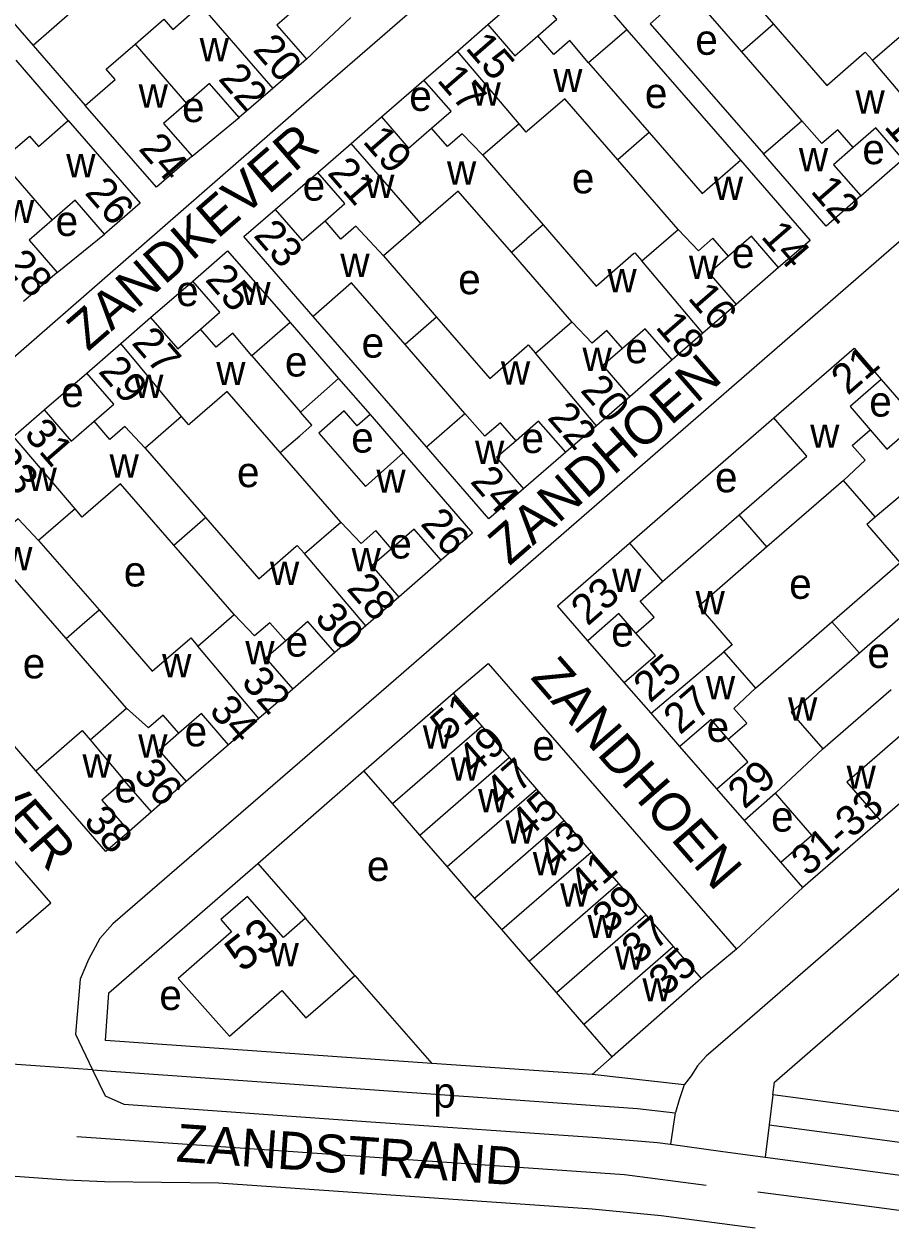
# Model space of a CAD drawing. Extents: x 155854 to 157362, y 383621 to 384685.
# Drawn here: x 156071.1 to 156185.4, y 383977 to 384135.3 of the extents above; entities that cross this region are included whole.
import ezdxf

# ---------------------------------------------------------------- set-up
doc = ezdxf.new("R2010")
doc.units = 0
for name, color, linetype in [('BLT_Basislijn', 7, 'Continuous'), ('BLT_Bebouwing', 7, 'Continuous'), ('BLT_Centroide', 7, 'Continuous'), ('BLT_Huisnummer', 7, 'Continuous'), ('BLT_Huisnummer_ tussenligend', 7, 'Continuous'), ('BLT_Huisnummer_reeks', 7, 'Continuous'), ('BLT_Onderverdeling_panden', 7, 'Continuous'), ('BLT_Straatnaam', 7, 'Continuous'), ('BLT_Vlakafsluiter', 7, 'Continuous')]:
    doc.layers.add(name, color=color, linetype=linetype)

msp = doc.modelspace()

# ---------------------------------------------------------------- linework, layer by layer
at = {"layer": 'BLT_Basislijn'}
for p, q in [((156182.59, 384189.41), (156111.16, 384127.33)), ((156228.99, 384143.37), (156119.21, 384047.9)), ((156132.32, 384135.17), (156137.86, 384139.98)), ((156080.23, 384139.36), (156072.3, 384132.42)), ((156108.36, 384130.6), (156114.21, 384136.12)), ((156153.72, 384135.29), (156168.72, 384118.08)), ((156150.68, 384134.48), (156165.66, 384117.25)), ((156072.3, 384132.42), (156079.17, 384124.5)), ((156076.93, 384122.52), (156070.03, 384130.46)), ((156111.16, 384127.33), (155991.68, 384023.17)), ((156118.28, 384122.97), (156123.88, 384127.84)), ((156093.27, 384117.78), (156099.48, 384122.89)), ((156181.54, 384112.55), (156187.1, 384117.41)), ((156104.24, 384110.77), (156109.85, 384115.65)), ((156075.46, 384102.45), (156081.72, 384107.5)), ((156170.68, 384103.1), (156165.08, 384098.22)), ((156087.8, 384096.48), (156093.36, 384101.29)), ((156106.2, 384095.82), (156112.6, 384088.45)), ((156124.22, 384079.4), (156109.27, 384096.63)), ((156156.64, 384090.89), (156151.04, 384086.03)), ((156073.76, 384084.28), (156079.36, 384089.14)), ((156184.24, 384088.28), (156189.1, 384082.69)), ((156116.76, 384083.66), (156121.15, 384078.61)), ((156151, 384066.68), (156170.05, 384083.24)), ((156142.6, 384078.7), (156137.04, 384073.86)), ((156126.15, 384064.42), (156120.57, 384059.57)), ((156150.32, 384048.28), (156145.51, 384053.8)), ((156112.13, 384052.23), (156106.56, 384047.39)), ((156127.74, 384046.86), (156132.34, 384050.8)), ((156203.42, 384046.86), (156184.1, 384030.05)), ((156072.64, 384036.63), (156066.69, 384043.48)), ((156098.08, 384040.05), (156092.49, 384035.2)), ((156162.53, 384034.22), (156157.67, 384039.83)), ((156101.95, 384024.4), (156115.95, 384036.63)), ((156087.9, 384031.2), (156084.96, 384028.62)), ((156170.97, 384024.54), (156166.17, 384030.06)), ((156101.95, 384024.4), (156108.25, 384017.14)), ((156173.9, 384021.19), (156165.13, 384013.05)), ((156114.76, 384009.61), (156124.9, 383997.99)), ((156158.22, 383995.14), (156146.09, 383996.5)), ((156169.94, 383993.83), (156169.45, 383989.86)), ((156169.45, 383989.86), (156168.92, 383985.6))]:
    msp.add_line(p, q, dxfattribs=at)
for points in [[(156150.65, 384224.45), (156146.11, 384229.67), (156055.9, 384151.3), (156072.3, 384132.42)], [(156271.3, 384094.61), (156165.88, 384003.01), (156161.13, 383998.95)], [(156169.94, 383993.83), (156170.15, 383995.49), (156269.03, 384081.38)], [(156070.04, 384015.24), (156074.62, 384019.2), (156041.83, 384056.94), (156037.26, 384052.98)], [(156132.34, 384050.8), (156165.13, 384013.05)], [(156119.21, 384047.9), (156082.8, 384016.41), (156081.09, 384014.48), (156079.59, 384011.7), (156078.52, 384009.12), (156077.88, 384001.84), (156080.14, 383997.12)], [(156081.83, 384001.02), (156082.27, 384007.3), (156101.95, 384024.4)], [(156165.13, 384013.05), (156160.47, 384009.18)], [(156124.9, 383997.99), (156081.83, 384001.02)], [(156161.13, 383998.95), (156159.98, 383997.65), (156159.15, 383996.34), (156158.22, 383995.14)], [(156146.09, 383996.5), (156124.9, 383997.99)], [(156148.71, 383998.87), (156146.09, 383996.5)], [(156080.14, 383997.12), (156081.78, 383993.72), (156084.26, 383992.58)], [(156080.14, 383997.12), (156152.08, 383992.01), (156157.06, 383991.45)], [(156158.22, 383995.14), (156157.57, 383993.18), (156157.09, 383991.48)], [(156158.06, 383994.64), (156158.05, 383994.63)], [(156084.26, 383992.58), (156116.24, 383990.33), (156146.75, 383988.19)], [(156208.6, 383988.69), (156169.94, 383993.83)], [(156157.06, 383991.45), (156156.41, 383987.31)], [(156169.45, 383989.86), (156266.3, 383977), (156363.4, 383964.11)], [(156078.08, 383988.34), (156150.36, 383983.33), (156161.14, 383981.92)], [(156146.75, 383988.19), (156154.72, 383987.54), (156156.41, 383987.31)], [(156156.41, 383987.31), (156163.02, 383986.39), (156168.92, 383985.6)], [(156168.92, 383985.6), (156189.73, 383982.81)], [(156167.61, 383976.23), (156155.21, 383977.85), (156146.07, 383978.71), (156096.76, 383982.18), (156081.71, 383982.35), (156076.66, 383982.58), (156069.91, 383983.06), (156060.92, 383984.14)], [(156167.95, 383981.03), (156181.65, 383979.24), (156217.42, 383974.51), (156229.18, 383972.97)]]:
    msp.add_lwpolyline(points, dxfattribs=at)
at = {"layer": 'BLT_Bebouwing'}
for p, q in [((156128.3, 384131.68), (156132.32, 384135.17)), ((156108.36, 384130.6), (156103.92, 384126.74)), ((156123.88, 384127.84), (156128.3, 384131.68)), ((156103.92, 384126.74), (156099.48, 384122.89)), ((156114.26, 384119.48), (156118.28, 384122.97)), ((156109.85, 384115.65), (156114.26, 384119.48)), ((156100.09, 384107.17), (156104.24, 384110.77)), ((156123.47, 384108.9), (156118.53, 384104.62)), ((156109.27, 384096.63), (156100.09, 384107.17)), ((156118.53, 384104.62), (156125.55, 384096.53)), ((156075.46, 384102.45), (156071.02, 384098.59)), ((156165.08, 384098.22), (156160.69, 384094.4)), ((156083.85, 384093.05), (156087.8, 384096.48)), ((156160.69, 384094.4), (156156.64, 384090.89)), ((156079.36, 384089.14), (156083.85, 384093.05)), ((156101.14, 384091.43), (156107.59, 384084)), ((156107.59, 384084), (156112.6, 384088.45)), ((156112.6, 384088.45), (156116.76, 384083.66)), ((156151.04, 384086.03), (156146.64, 384082.2)), ((156069.72, 384080.79), (156073.76, 384084.28)), ((156146.64, 384082.2), (156142.6, 384078.7)), ((156120.57, 384059.57), (156116.22, 384055.78)), ((156116.22, 384055.78), (156112.13, 384052.23)), ((156106.56, 384047.39), (156102.1, 384043.53)), ((156115.95, 384036.63), (156127.74, 384046.86)), ((156127.74, 384046.86), (156131.51, 384042.52)), ((156102.1, 384043.53), (156098.08, 384040.05)), ((156131.52, 384042.52), (156135.12, 384038.37)), ((156135.12, 384038.36), (156138.74, 384034.2)), ((156087.9, 384031.2), (156084.33, 384035.31)), ((156119.72, 384032.29), (156115.95, 384036.63)), ((156092.49, 384035.2), (156087.9, 384031.2)), ((156138.74, 384034.2), (156142.35, 384030.04)), ((156123.32, 384028.14), (156119.72, 384032.29)), ((156142.35, 384030.04), (156145.95, 384025.89)), ((156126.94, 384023.97), (156123.32, 384028.14)), ((156145.95, 384025.89), (156149.56, 384021.74)), ((156130.55, 384019.81), (156126.94, 384023.97)), ((156149.56, 384021.74), (156153.17, 384017.59)), ((156100.59, 384020.03), (156097.06, 384016.97)), ((156105.34, 384014.59), (156100.59, 384020.03)), ((156134.15, 384015.66), (156130.55, 384019.81)), ((156097.06, 384016.97), (156098.48, 384015.36)), ((156108.25, 384017.14), (156105.34, 384014.59)), ((156114.76, 384009.61), (156108.25, 384017.14)), ((156153.17, 384017.59), (156156.78, 384013.43)), ((156098.48, 384015.36), (156091.44, 384009.19)), ((156137.76, 384011.49), (156134.15, 384015.66)), ((156156.78, 384013.43), (156160.47, 384009.18)), ((156141.37, 384007.34), (156137.76, 384011.49)), ((156091.44, 384009.19), (156098.19, 384001.58)), ((156108.3, 384004.01), (156114.76, 384009.61)), ((156160.47, 384009.18), (156148.71, 383998.87)), ((156098.19, 384001.58), (156105.14, 384007.63)), ((156105.14, 384007.63), (156108.3, 384004.01)), ((156144.98, 384003.18), (156141.37, 384007.34)), ((156148.71, 383998.87), (156144.98, 384003.18))]:
    msp.add_line(p, q, dxfattribs=at)
for points in [[(156137.86, 384139.98), (156142.46, 384143.98), (156150.68, 384134.48)], [(156162.05, 384144.39), (156170.02, 384135.21)], [(156138.9, 384133.67), (156141.44, 384135.87), (156137.86, 384139.98)], [(156165.85, 384131.58), (156158.75, 384139.74), (156153.72, 384135.29)], [(156085.74, 384132.59), (156089.53, 384135.88), (156090.71, 384134.52), (156094.39, 384137.72)], [(156107.5, 384137.72), (156104.46, 384135.08), (156108.14, 384130.85), (156108.36, 384130.6)], [(156132.32, 384135.17), (156135.89, 384131.06), (156138.9, 384133.67)], [(156170.02, 384135.21), (156177.05, 384127.13), (156181.99, 384131.43)], [(156150.68, 384134.48), (156145.6, 384130.12)], [(156183.08, 384130.45), (156187.88, 384134.62)], [(156079.17, 384124.5), (156083.12, 384127.93), (156081.93, 384129.29), (156085.74, 384132.59)], [(156173.77, 384122.47), (156165.85, 384131.58)], [(156181.99, 384131.43), (156182.13, 384131.54), (156183.08, 384130.45)], [(156145.6, 384130.12), (156153.61, 384120.91)], [(156099.48, 384122.89), (156095.59, 384127.37), (156092.55, 384124.74)], [(156124.87, 384121.48), (156127.46, 384123.73), (156123.88, 384127.84)], [(156093.27, 384117.78), (156088.57, 384113.69), (156079.17, 384124.5)], [(156092.55, 384124.74), (156089.52, 384122.1), (156093.27, 384117.78)], [(156149.47, 384117.3), (156142.46, 384125.38), (156137.51, 384121.1)], [(156068.01, 384117.16), (156071.8, 384120.45), (156072.99, 384119.09), (156076.93, 384122.52)], [(156076.93, 384122.52), (156086.42, 384111.58), (156081.72, 384107.5)], [(156118.28, 384122.97), (156121.86, 384118.86), (156124.87, 384121.48)], [(156168.72, 384118.08), (156173.77, 384122.47)], [(156136.43, 384122.07), (156131.63, 384117.91)], [(156137.51, 384121.1), (156137.38, 384120.98), (156136.43, 384122.07)], [(156153.61, 384120.91), (156160.6, 384112.86), (156165.66, 384117.25)], [(156187.1, 384117.41), (156183.52, 384121.52), (156180.55, 384118.92)], [(156131.63, 384117.91), (156139.6, 384108.72)], [(156181.54, 384112.55), (156176.97, 384108.55), (156168.72, 384118.08)], [(156180.55, 384118.92), (156177.95, 384116.65), (156181.54, 384112.55)], [(156157.44, 384108.12), (156149.47, 384117.3)], [(156165.66, 384117.25), (156174.84, 384106.67), (156170.68, 384103.1)], [(156110.82, 384109.27), (156113.42, 384111.53), (156109.85, 384115.65)], [(156135.43, 384105.1), (156128.41, 384113.19), (156123.47, 384108.9)], [(156081.72, 384107.5), (156077.85, 384111.96), (156074.81, 384109.32)], [(156104.24, 384110.77), (156107.81, 384106.66), (156110.82, 384109.27)], [(156074.81, 384109.32), (156071.78, 384106.68), (156075.46, 384102.45)], [(156139.6, 384108.72), (156146.62, 384100.64), (156151.56, 384104.93)], [(156152.64, 384103.96), (156157.44, 384108.12)], [(156170.68, 384103.1), (156167.13, 384107.24), (156164.1, 384104.6)], [(156093.36, 384101.29), (156097.93, 384105.29), (156106.2, 384095.82)], [(156143.39, 384095.93), (156135.43, 384105.1)], [(156151.56, 384104.93), (156151.7, 384105.04), (156152.64, 384103.96)], [(156164.1, 384104.6), (156161.51, 384102.33), (156165.08, 384098.22)], [(156094.37, 384094.96), (156096.94, 384097.18), (156093.36, 384101.29)], [(156121.38, 384092.91), (156114.3, 384101.06), (156109.27, 384096.63)], [(156087.8, 384096.48), (156091.37, 384092.36), (156094.37, 384094.96)], [(156106.2, 384095.82), (156101.14, 384091.43)], [(156125.55, 384096.53), (156132.57, 384088.45), (156137.51, 384092.74)], [(156138.59, 384091.77), (156143.39, 384095.93)], [(156156.64, 384090.89), (156153.07, 384095.01), (156150.08, 384092.41)], [(156129.29, 384083.81), (156121.38, 384092.91)], [(156137.51, 384092.74), (156137.65, 384092.86), (156138.59, 384091.77)], [(156150.08, 384092.41), (156147.47, 384090.14), (156151.04, 384086.03)], [(156170.05, 384083.24), (156180.65, 384092.45), (156184.24, 384088.28)], [(156080.35, 384082.78), (156082.93, 384085.03), (156079.36, 384089.14)], [(156184.24, 384088.28), (156180.12, 384084.72), (156182.78, 384081.65)], [(156104.92, 384078.64), (156097.9, 384086.72), (156092.96, 384082.43)], [(156073.76, 384084.28), (156077.33, 384080.15), (156080.35, 384082.78)], [(156091.88, 384083.41), (156087.08, 384079.24)], [(156092.96, 384082.43), (156092.83, 384082.31), (156091.88, 384083.41)], [(156116.76, 384083.66), (156115.08, 384082.2), (156113.35, 384084.17), (156110.02, 384081.21), (156116.15, 384074.16), (156121.15, 384078.61)], [(156124.22, 384079.4), (156129.29, 384083.81)], [(156142.6, 384078.7), (156139.02, 384082.81), (156136.04, 384080.22)], [(156165.49, 384070.41), (156174.44, 384078.18), (156170.05, 384083.24)], [(156182.78, 384081.65), (156184.99, 384079.11), (156189.1, 384082.69)], [(156136.04, 384080.22), (156133.46, 384077.98), (156137.04, 384073.86)], [(156087.08, 384079.24), (156095.05, 384070.06)], [(156112.89, 384069.46), (156104.92, 384078.64)], [(156121.15, 384078.61), (156130.3, 384068), (156126.15, 384064.42)], [(156137.04, 384073.86), (156132.45, 384069.89), (156124.22, 384079.4)], [(156179.28, 384074.97), (156169.16, 384066.18)], [(156183.45, 384070.17), (156179.28, 384074.97)], [(156090.87, 384066.43), (156083.84, 384074.52), (156078.9, 384070.23)], [(156077.82, 384071.2), (156073.02, 384067.03)], [(156078.9, 384070.23), (156078.77, 384070.11), (156077.82, 384071.2)], [(156155.38, 384061.63), (156165.49, 384070.41)], [(156182.46, 384069.07), (156182.34, 384069.21), (156183.45, 384070.17)], [(156095.05, 384070.06), (156102.08, 384061.98), (156107.01, 384066.27)], [(156108.09, 384065.3), (156112.89, 384069.46)], [(156126.15, 384064.42), (156122.59, 384068.54), (156119.61, 384065.95)], [(156177.74, 384056.31), (156186.75, 384064.13), (156182.46, 384069.07)], [(156073.02, 384067.03), (156080.99, 384057.86)], [(156098.83, 384057.26), (156090.87, 384066.43)], [(156107.01, 384066.27), (156107.15, 384066.38), (156108.09, 384065.3)], [(156119.61, 384065.95), (156116.99, 384063.68), (156120.57, 384059.57)], [(156145.51, 384053.8), (156141.49, 384058.4), (156151, 384066.68)], [(156151, 384066.68), (156155.38, 384061.63)], [(156169.16, 384066.18), (156160.16, 384058.36), (156164.57, 384053.28)], [(156076.63, 384054.1), (156069.61, 384062.18), (156064.78, 384057.98)], [(156191.44, 384060.91), (156181.36, 384052.14)], [(156080.99, 384057.86), (156088.02, 384049.77), (156092.96, 384054.06)], [(156094.03, 384053.09), (156098.83, 384057.26)], [(156112.13, 384052.23), (156108.56, 384056.34), (156105.63, 384053.8)], [(156151.86, 384054.82), (156149.61, 384057.39), (156145.51, 384053.8)], [(156167.63, 384047.52), (156177.74, 384056.31)], [(156150.32, 384048.28), (156154.43, 384051.86), (156151.86, 384054.82)], [(156084.63, 384044.9), (156076.63, 384054.1)], [(156092.96, 384054.06), (156093.09, 384054.18), (156094.03, 384053.09)], [(156105.63, 384053.8), (156103, 384051.51), (156106.56, 384047.39)], [(156164.57, 384053.28), (156163.46, 384052.32)], [(156163.46, 384052.32), (156167.63, 384047.52)], [(156181.36, 384052.14), (156172.35, 384044.32), (156176.52, 384039.53)], [(156153.85, 384044.22), (156150.32, 384048.28)], [(156176.52, 384039.53), (156185.53, 384047.36)], [(156079.83, 384040.73), (156084.63, 384044.9)], [(156098.08, 384040.05), (156094.52, 384044.18), (156091.53, 384041.58)], [(156157.67, 384039.83), (156153.85, 384044.22)], [(156161.78, 384043.41), (156157.67, 384039.83)], [(156164.04, 384040.79), (156161.78, 384043.41)], [(156189.07, 384043.28), (156179.68, 384035.12), (156184.1, 384030.05)], [(156072.64, 384036.63), (156078.78, 384041.94), (156079.83, 384040.73)], [(156091.53, 384041.58), (156088.91, 384039.3), (156092.49, 384035.2)], [(156166.63, 384037.81), (156164.04, 384040.79)], [(156162.53, 384034.22), (156166.63, 384037.81)], [(156084.96, 384028.62), (156081.9, 384025.96), (156072.64, 384036.63)], [(156084.33, 384035.31), (156081.37, 384032.73), (156084.96, 384028.62)], [(156166.17, 384030.06), (156162.53, 384034.22)], [(156170.28, 384033.65), (156166.17, 384030.06)], [(156175.07, 384028.13), (156170.28, 384033.65)], [(156184.1, 384030.05), (156173.9, 384021.19)], [(156170.97, 384024.54), (156175.07, 384028.13)], [(156173.9, 384021.19), (156170.97, 384024.54)]]:
    msp.add_lwpolyline(points, dxfattribs=at)
at = {"layer": 'BLT_Onderverdeling_panden'}
for p, q in [((156094.39, 384137.72), (156103.92, 384126.74)), ((156085.74, 384132.59), (156092.55, 384124.74)), ((156136.43, 384122.07), (156128.31, 384131.68)), ((156191.13, 384120.92), (156183.08, 384130.45)), ((156123.47, 384108.9), (156114.26, 384119.48)), ((156068.01, 384117.16), (156074.81, 384109.32)), ((156160.69, 384094.4), (156152.64, 384103.96)), ((156125.55, 384096.53), (156121.38, 384092.91)), ((156091.88, 384083.41), (156083.85, 384093.05)), ((156146.64, 384082.2), (156138.59, 384091.77)), ((156077.82, 384071.2), (156069.72, 384080.79)), ((156183.45, 384070.17), (156193, 384078.22)), ((156169.16, 384066.18), (156165.49, 384070.41)), ((156116.22, 384055.78), (156108.09, 384065.3)), ((156181.36, 384052.14), (156177.74, 384056.31)), ((156102.1, 384043.53), (156094.03, 384053.09)), ((156153.85, 384044.22), (156163.46, 384052.32)), ((156119.72, 384032.29), (156131.52, 384042.52)), ((156079.83, 384040.73), (156084.33, 384035.31)), ((156170.28, 384033.65), (156176.52, 384039.53)), ((156123.32, 384028.14), (156135.12, 384038.36)), ((156126.94, 384023.97), (156138.74, 384034.2)), ((156130.55, 384019.81), (156142.35, 384030.04)), ((156134.15, 384015.66), (156145.95, 384025.89)), ((156137.76, 384011.49), (156149.56, 384021.74)), ((156141.37, 384007.34), (156153.17, 384017.59)), ((156144.98, 384003.18), (156156.78, 384013.43))]:
    msp.add_line(p, q, dxfattribs=at)
for points in [[(156170.02, 384135.21), (156165.85, 384131.58)], [(156145.6, 384130.12), (156143.12, 384133.06), (156141.02, 384131.23), (156138.9, 384133.67)], [(156180.55, 384118.92), (156178.5, 384121.28), (156176.39, 384119.45), (156173.77, 384122.47)], [(156131.63, 384117.91), (156128.93, 384120.76), (156126.97, 384119.06), (156124.87, 384121.48)], [(156153.61, 384120.91), (156151.94, 384119.45)], [(156151.94, 384119.45), (156149.47, 384117.3)], [(156118.53, 384104.62), (156114.89, 384108.56), (156112.92, 384106.85), (156110.82, 384109.27)], [(156139.6, 384108.72), (156137.46, 384106.87)], [(156164.1, 384104.6), (156162.03, 384106.97), (156160.12, 384105.29), (156157.44, 384108.12)], [(156135.43, 384105.1), (156137.46, 384106.87)], [(156150.08, 384092.41), (156148.02, 384094.79), (156146.07, 384093.1), (156143.39, 384095.93)], [(156101.14, 384091.43), (156098.63, 384094.43), (156096.46, 384092.55), (156094.37, 384094.96)], [(156087.08, 384079.24), (156084.38, 384082.09), (156082.42, 384080.39), (156080.35, 384082.78)], [(156107.48, 384080.88), (156109.09, 384082.28), (156107.59, 384084)], [(156136.04, 384080.22), (156133.98, 384082.59), (156131.91, 384080.8), (156129.29, 384083.81)], [(156179.28, 384074.97), (156182.11, 384077.66), (156180.42, 384079.6), (156182.78, 384081.65)], [(156104.92, 384078.64), (156107.48, 384080.88)], [(156073.02, 384067.03), (156070.3, 384069.89), (156068.38, 384068.21), (156066.3, 384070.61)], [(156090.87, 384066.43), (156095.05, 384070.07)], [(156119.61, 384065.95), (156117.53, 384068.34), (156115.57, 384066.63), (156112.89, 384069.46)], [(156151.86, 384054.82), (156154.27, 384056.92), (156152.44, 384059.03), (156155.38, 384061.63)], [(156078.76, 384055.93), (156080.99, 384057.86)], [(156076.63, 384054.1), (156078.76, 384055.93)], [(156105.63, 384053.8), (156103.52, 384056.17), (156101.51, 384054.43), (156098.83, 384057.26)], [(156164.04, 384040.79), (156166.48, 384042.91), (156164.8, 384044.84), (156167.63, 384047.52)], [(156091.53, 384041.58), (156089.45, 384043.98), (156087.5, 384042.29), (156084.63, 384044.9)]]:
    msp.add_lwpolyline(points, dxfattribs=at)
at = {"layer": 'BLT_Vlakafsluiter'}
msp.add_line((156080.14, 383997.12), (156066.34, 383998.09), dxfattribs=at)

# ---------------------------------------------------------------- texts
at = {"layer": 'BLT_Centroide'}
for s, p in [('w', (156094.27, 384130.31)), ('e', (156159.7, 384131.18)), ('w', (156140.94, 384126.25)), ('w', (156086.22, 384124.2)), ('w', (156130.16, 384124.48)), ('e', (156153.04, 384124.14)), ('e', (156121.94, 384123.77)), ('w', (156180.84, 384123.4)), ('e', (156091.95, 384122.29)), ('e', (156181.75, 384116.73)), ('w', (156076.66, 384115)), ('w', (156173.37, 384115.8)), ('w', (156126.92, 384114.03)), ('e', (156143.4, 384112.88)), ('e', (156107.87, 384111.92)), ('w', (156116.11, 384112.27)), ('w', (156162.14, 384112)), ('w', (156068.58, 384108.95)), ('e', (156075.25, 384107.25)), ('w', (156112.84, 384101.84)), ('e', (156164.52, 384103.03)), ('w', (156158.86, 384101.59)), ('e', (156128.4, 384099.56)), ('w', (156148.09, 384099.81)), ('e', (156091.17, 384097.99)), ('w', (156099.78, 384098.12)), ('e', (156115.65, 384091.18)), ('w', (156144.81, 384089.41)), ('e', (156150.45, 384090.44)), ('e', (156105.53, 384088.69)), ('w', (156134.04, 384087.62)), ('w', (156096.46, 384087.56)), ('e', (156075.99, 384084.66)), ('w', (156085.62, 384085.86)), ('e', (156182.66, 384083.4)), ('e', (156114.28, 384078.64)), ('e', (156136.75, 384078.59)), ('w', (156174.86, 384079.28)), ('w', (156130.62, 384077.14)), ('w', (156082.38, 384075.34)), ('w', (156071.56, 384073.58)), ('e', (156099.2, 384074.08)), ('e', (156162.3, 384073.4)), ('w', (156117.6, 384073.34)), ('e', (156119.31, 384064.66)), ('w', (156068.33, 384063.09)), ('w', (156114.33, 384062.97)), ('e', (156084.26, 384060.96)), ('w', (156103.55, 384061.16)), ('w', (156148.71, 384060.25)), ('e', (156172.09, 384059.33)), ('w', (156159.73, 384057.3)), ('e', (156148.6, 384053.03)), ('e', (156105.61, 384051.7)), ('w', (156100.3, 384050.69)), ('e', (156182.41, 384050.2)), ('e', (156070.92, 384048.83)), ('w', (156089.32, 384048.97)), ('w', (156161.09, 384046.06)), ('w', (156171.94, 384043.25)), ('e', (156161.19, 384040.44)), ('e', (156092.28, 384039.85)), ('w', (156123.73, 384039.56)), ('w', (156086.16, 384038.36)), ('e', (156138.19, 384037.99)), ('w', (156078.8, 384035.72)), ('w', (156127.41, 384035.31)), ('w', (156179.67, 384034.25)), ('e', (156083.03, 384032.44)), ('w', (156131.02, 384031.16)), ('e', (156169.7, 384028.59)), ('w', (156134.64, 384027)), ('w', (156138.24, 384022.84)), ('e', (156116.35, 384022.07)), ('w', (156141.86, 384018.69)), ('w', (156145.46, 384014.53)), ('w', (156103.5, 384010.81)), ('w', (156149.07, 384010.38)), ('w', (156152.71, 384006.16)), ('e', (156088.95, 384005.03)), ('p', (156125.1, 383992.14))]:
    msp.add_text(s, height=4, dxfattribs=at).set_placement(p)
at = {"layer": 'BLT_Huisnummer'}
for s, height, rotation, p in [('17', 4, 310.9773, (156125.49, 384127.77)), ('24', 4, 310.9768, (156086.09, 384118.71)), ('21', 4, 310.9773, (156111.01, 384115.51)), ('26', 4, 310.9768, (156078.99, 384112.89)), ('12', 4, 310.9798, (156174.8, 384113.11)), ('23', 4, 310.9773, (156101.27, 384107.26)), ('14', 4, 310.9798, (156168.24, 384107.12)), ('25', 4, 310.9773, (156094.88, 384101.44)), ('18', 4, 310.9798, (156154.33, 384095.17)), ('21', 4, 40.9807, (156179.82, 384086.11)), ('29', 4, 310.9773, (156080.78, 384089.3)), ('33', 4, 310.9773, (156066.4, 384077.27)), ('24', 4, 310.9798, (156129.87, 384074.77)), ('26', 4, 310.9798, (156123.3, 384069.18)), ('23', 4, 40.9807, (156145.48, 384055.65)), ('32', 4, 310.9798, (156099.63, 384048.28)), ('27', 4, 40.9807, (156157.68, 384041.28)), ('51', 4, 40.9807, (156126.92, 384040.37)), ('45', 4, 40.9807, (156137.43, 384027.45)), ('38', 4, 310.9798, (156078.82, 384029.89)), ('41', 4, 40.9807, (156145.2, 384019.46)), ('53', 4.5, 38.4324, (156099.9, 384009.89)), ('35', 4, 40.9807, (156155.74, 384006.7))]:
    msp.add_text(s, height=height, rotation=rotation, dxfattribs=at).set_placement(p)
at = {"layer": 'BLT_Huisnummer_ tussenligend'}
for s, rotation, p in [('20', 310.9768, (156101.17, 384131.77)), ('15', 310.9773, (156129.25, 384132.02)), ('22', 310.9768, (156096.62, 384127.96)), ('10', 310.9798, (156184.5, 384121.62)), ('19', 310.9773, (156115.68, 384119.68)), ('28', 310.9768, (156068.23, 384103.35)), ('16', 310.9798, (156158.59, 384099)), ('27', 310.9773, (156085.18, 384093.08)), ('20', 310.9798, (156144.41, 384086.81)), ('22', 310.9798, (156140.05, 384083.2)), ('31', 310.9773, (156070.97, 384081)), ('28', 310.9798, (156113.55, 384060.63)), ('30', 310.9798, (156109.32, 384056.73)), ('25', 40.9807, (156153.72, 384045.49)), ('34', 310.9798, (156095.4, 384044.48)), ('49', 40.9807, (156130.49, 384035.93)), ('36', 310.9798, (156085.39, 384036.15)), ('47', 40.9807, (156134.12, 384031.7)), ('29', 40.9807, (156166.18, 384031.45)), ('43', 40.9807, (156141.02, 384023.42)), ('39', 40.9807, (156148.29, 384015.01)), ('37', 40.9807, (156152.15, 384010.89))]:
    msp.add_text(s, height=4, rotation=rotation, dxfattribs=at).set_placement(p)
at = {"layer": 'BLT_Huisnummer_reeks'}
msp.add_text('31-33', height=4, rotation=40.9825, dxfattribs=at).set_placement((156174.53, 384022.56))
at = {"layer": 'BLT_Straatnaam'}
for s, rotation, p in [('ZANDKEVER', 40.9819, (156079.53, 384091.92)), ('ZANDHOEN', 40.9821, (156135.16, 384063.61)), ('ZANDKEVER', 310.9821, (156047.73, 384053.96)), ('ZANDHOEN', 310.9821, (156137.83, 384048.89)), ('ZANDSTRAND', 355.9812, (156091.07, 383985.03))]:
    msp.add_text(s, height=5, rotation=rotation, dxfattribs=at).set_placement(p)

doc.saveas('drawing.dxf')
